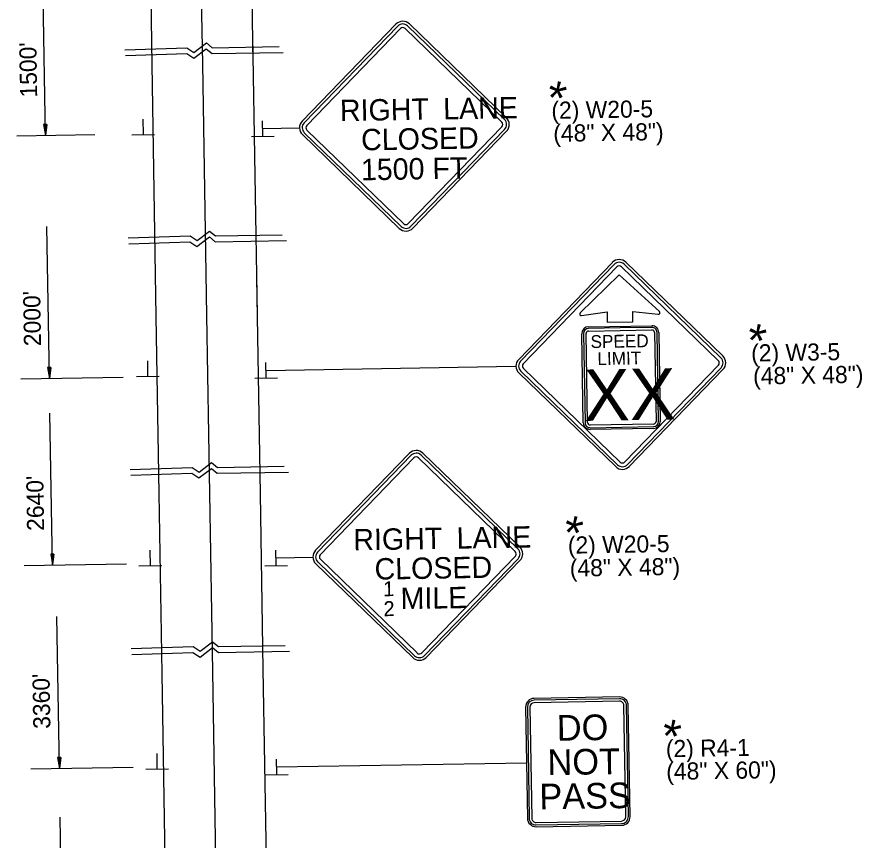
# Model space of a CAD drawing. Extents: x 1676639 to 1677883, y 226447 to 231777.
# Drawn here: x 1677068.7 to 1677365.1, y 228691.4 to 228980 of the extents above; entities that cross this region are included whole.
import ezdxf

# ---------------------------------------------------------------- set-up
doc = ezdxf.new("R2010")
doc.units = 0
for name, color, linetype in [('Default', 7, 'Continuous'), ('P_TC_Signs_Permanent', 7, 'Continuous'), ('P_TC_Signs_Temporary', 7, 'Continuous'), ('R_Annotation', 7, 'Continuous')]:
    doc.layers.add(name, color=color, linetype=linetype)

msp = doc.modelspace()

# ---------------------------------------------------------------- linework, layer by layer
at = {"layer": 'Default'}
for p, q in [((1677116.11, 228963.33), (1677113.41, 229126.42)), ((1677133.84, 228963.62), (1677131.14, 229126.72)), ((1677151.57, 228963.92), (1677148.87, 229127.01)), ((1677078.66, 228938.47), (1677077.78, 228991.7)), ((1677153.03, 228875.59), (1677151.41, 228973.27)), ((1677117.57, 228875.01), (1677116.11, 228963.33)), ((1677135.3, 228875.3), (1677133.84, 228963.62)), ((1677079.17, 228942.31), (1677078.02, 228942.29)), ((1677078.02, 228942.29), (1677078.66, 228938.47)), ((1677078.12, 228942.29), (1677078.65, 228939.11)), ((1677078.21, 228942.29), (1677078.64, 228939.77)), ((1677078.31, 228942.29), (1677078.63, 228940.41)), ((1677078.41, 228942.29), (1677078.62, 228941.05)), ((1677078.5, 228942.3), (1677078.6, 228941.69)), ((1677078.68, 228942.3), (1677078.6, 228941.69)), ((1677078.78, 228942.3), (1677078.62, 228941.05)), ((1677078.88, 228942.3), (1677078.63, 228940.41)), ((1677078.97, 228942.3), (1677078.64, 228939.77)), ((1677079.07, 228942.31), (1677078.65, 228939.11)), ((1677079.17, 228942.31), (1677078.66, 228938.47)), ((1677113.02, 228938.77), (1677112.93, 228944.22)), ((1677154.92, 228938.18), (1677154.83, 228943.62)), ((1677068.67, 228938.31), (1677096.05, 228938.76)), ((1677116.99, 228938.72), (1677109.01, 228938.59)), ((1677158.89, 228938.13), (1677150.91, 228937.99)), ((1677080.07, 228853.29), (1677079.19, 228906.51)), ((1677154.07, 228812.85), (1677152.82, 228888.67)), ((1677118.6, 228812.95), (1677117.57, 228875.01)), ((1677136.34, 228812.9), (1677135.3, 228875.3)), ((1677114.64, 228853.98), (1677114.55, 228859.43)), ((1677156.11, 228853.38), (1677156.02, 228858.83)), ((1677080.58, 228857.12), (1677079.43, 228857.11)), ((1677079.43, 228857.11), (1677080.07, 228853.29)), ((1677079.53, 228857.11), (1677080.06, 228853.93)), ((1677079.63, 228857.11), (1677080.05, 228854.59)), ((1677079.72, 228857.11), (1677080.04, 228855.22)), ((1677079.82, 228857.11), (1677080.03, 228855.87)), ((1677079.92, 228857.11), (1677080.02, 228856.51)), ((1677080.1, 228857.12), (1677080.02, 228856.51)), ((1677080.19, 228857.12), (1677080.03, 228855.87)), ((1677080.29, 228857.12), (1677080.04, 228855.22)), ((1677080.39, 228857.12), (1677080.05, 228854.59)), ((1677080.48, 228857.12), (1677080.06, 228853.93)), ((1677080.58, 228857.12), (1677080.07, 228853.29)), ((1677070.08, 228853.13), (1677105.99, 228853.72)), ((1677118.61, 228853.93), (1677110.63, 228853.8)), ((1677160.08, 228853.33), (1677152.1, 228853.2)), ((1677081.15, 228787.86), (1677080.27, 228841.08)), ((1677119.65, 228749.75), (1677118.6, 228812.95)), ((1677137.37, 228750.51), (1677136.34, 228812.9)), ((1677155.09, 228751.27), (1677154.07, 228812.85)), ((1677081.66, 228791.69), (1677080.52, 228791.67)), ((1677080.52, 228791.67), (1677081.15, 228787.86)), ((1677080.61, 228791.67), (1677081.14, 228788.5)), ((1677080.71, 228791.68), (1677081.13, 228789.15)), ((1677080.81, 228791.68), (1677081.12, 228789.79)), ((1677080.9, 228791.68), (1677081.11, 228790.44)), ((1677081, 228791.68), (1677081.1, 228791.08)), ((1677081.18, 228791.68), (1677081.1, 228791.08)), ((1677081.28, 228791.68), (1677081.11, 228790.44)), ((1677081.38, 228791.69), (1677081.12, 228789.79)), ((1677081.47, 228791.69), (1677081.13, 228789.15)), ((1677081.57, 228791.69), (1677081.14, 228788.5)), ((1677081.66, 228791.69), (1677081.15, 228787.86)), ((1677115.5, 228787.61), (1677115.41, 228793.06)), ((1677159.63, 228787.66), (1677159.54, 228793.1)), ((1677071.17, 228787.69), (1677107.08, 228788.29)), ((1677119.47, 228787.56), (1677111.49, 228787.43)), ((1677163.6, 228787.61), (1677155.62, 228787.47)), ((1677083.56, 228716.52), (1677082.68, 228769.75)), ((1677120.9, 228674.34), (1677119.65, 228749.75)), ((1677138.63, 228674.64), (1677137.37, 228750.51)), ((1677156.36, 228674.93), (1677155.09, 228751.27)), ((1677084.07, 228720.36), (1677082.92, 228720.34)), ((1677082.92, 228720.34), (1677083.56, 228716.52)), ((1677083.02, 228720.34), (1677083.55, 228717.16)), ((1677083.12, 228720.34), (1677083.54, 228717.82)), ((1677083.21, 228720.34), (1677083.53, 228718.46)), ((1677083.31, 228720.35), (1677083.52, 228719.11)), ((1677083.41, 228720.35), (1677083.51, 228719.74)), ((1677083.59, 228720.35), (1677083.51, 228719.74)), ((1677083.68, 228720.35), (1677083.52, 228719.11)), ((1677083.78, 228720.35), (1677083.53, 228718.46)), ((1677083.88, 228720.35), (1677083.54, 228717.82)), ((1677083.98, 228720.36), (1677083.55, 228717.16)), ((1677084.07, 228720.36), (1677083.56, 228716.52)), ((1677117.91, 228716.28), (1677117.82, 228721.73)), ((1677159.82, 228714.35), (1677159.73, 228719.79)), ((1677073.58, 228716.36), (1677109.48, 228716.95)), ((1677121.88, 228716.23), (1677113.9, 228716.1)), ((1677163.79, 228714.3), (1677155.81, 228714.16)), ((1677084.73, 228646.15), (1677083.84, 228699.37))]:
    msp.add_line(p, q, dxfattribs=at)
for points in [[(1677106.57, 228968.51), (1677128.3, 228969.2), (1677130.79, 228967.59), (1677135.15, 228970.89), (1677137.22, 228969.22), (1677160.64, 228969.61)], [(1677106.8, 228966.48), (1677128.25, 228967.17), (1677130.74, 228965.55), (1677135.1, 228968.85), (1677137.16, 228967.19), (1677162.11, 228967.59)], [(1677107.67, 228902.52), (1677129.39, 228903.22), (1677131.88, 228901.6), (1677136.24, 228904.9), (1677138.31, 228903.24), (1677161.73, 228903.62)], [(1677107.89, 228900.49), (1677129.34, 228901.18), (1677131.83, 228899.56), (1677136.19, 228902.86), (1677138.26, 228901.2), (1677163.2, 228901.6)], [(1677108.37, 228821.37), (1677130.09, 228822.06), (1677132.58, 228820.45), (1677136.94, 228823.75), (1677139.01, 228822.08), (1677162.43, 228822.47)], [(1677108.6, 228819.34), (1677130.04, 228820.02), (1677132.53, 228818.41), (1677136.89, 228821.71), (1677138.96, 228820.04), (1677163.9, 228820.45)], [(1677108.74, 228758.53), (1677130.47, 228759.22), (1677132.96, 228757.6), (1677137.32, 228760.9), (1677139.38, 228759.24), (1677162.81, 228759.62)], [(1677108.97, 228756.5), (1677130.41, 228757.18), (1677132.9, 228755.57), (1677137.27, 228758.87), (1677139.33, 228757.2), (1677164.28, 228757.61)]]:
    msp.add_lwpolyline(points, dxfattribs=at)
at = {"layer": 'P_TC_Signs_Permanent'}
for p, q in [((1677277.53, 228893.92), (1677244.67, 228859.96)), ((1677278.2, 228893.27), (1677245.35, 228859.31)), ((1677279.14, 228892.35), (1677246.29, 228858.39)), ((1677314.69, 228859.53), (1677280.73, 228892.38)), ((1677315.61, 228860.47), (1677281.65, 228893.32)), ((1677316.26, 228861.15), (1677282.3, 228894)), ((1677269.18, 228871.39), (1677291.38, 228871.75)), ((1677267.34, 228837.75), (1677266.82, 228868.95)), ((1677293.82, 228869.39), (1677294.34, 228838.2)), ((1677245.4, 228855.86), (1677279.36, 228823.01)), ((1677246.32, 228856.8), (1677280.28, 228823.95)), ((1677281.87, 228823.98), (1677314.72, 228857.94)), ((1677282.81, 228823.06), (1677315.66, 228857.02)), ((1677283.48, 228822.41), (1677316.34, 228856.37)), ((1677244.75, 228855.19), (1677278.71, 228822.33)), ((1677291.98, 228835.76), (1677269.78, 228835.39)), ((1677280.05, 228741.57), (1677250.06, 228741.07)), ((1677280.06, 228740.97), (1677250.07, 228740.47)), ((1677280.08, 228740.07), (1677250.08, 228739.57)), ((1677247.11, 228738.02), (1677247.75, 228699.03)), ((1677247.71, 228738.03), (1677248.35, 228699.04)), ((1677248.61, 228738.05), (1677249.25, 228699.05)), ((1677282.25, 228699.6), (1677281.6, 228738.59)), ((1677283.15, 228699.61), (1677282.5, 228738.61)), ((1677283.75, 228699.62), (1677283.1, 228738.62)), ((1677250.78, 228697.58), (1677280.77, 228698.07)), ((1677250.79, 228696.68), (1677280.79, 228697.17)), ((1677250.8, 228696.08), (1677280.8, 228696.57))]:
    msp.add_line(p, q, dxfattribs=at)
for points in [[(1677294.04, 228876.71), (1677279.95, 228889.57), (1677266.29, 228876.25)], [(1677266.76, 228875.29), (1677275.7, 228876.56), (1677275.76, 228873), (1677284.76, 228873.15), (1677284.7, 228876.7), (1677293.6, 228875.74)], [(1677291.39, 228871.15), (1677280.29, 228870.97), (1677269.19, 228870.79)], [(1677267.42, 228868.96), (1677267.94, 228837.76)], [(1677268.84, 228837.78), (1677268.32, 228868.97)], [(1677269.21, 228869.89), (1677280.31, 228870.07), (1677291.41, 228870.25)], [(1677292.32, 228869.37), (1677292.84, 228838.17)], [(1677293.74, 228838.19), (1677293.22, 228869.38)], [(1677291.95, 228837.26), (1677269.76, 228836.89)], [(1677269.77, 228835.99), (1677291.97, 228836.36)]]:
    msp.add_lwpolyline(points, dxfattribs=at)
for centre, radius, start, end in [((1677279.95, 228891.57), 3.38, 45.9497, 135.9497), ((1677279.95, 228891.57), 2.44, 45.9497, 135.9497), ((1677279.95, 228891.57), 1.13, 45.9497, 135.9497), ((1677293.66, 228876.3), 0.563, 263.8247, 47.6381), ((1677266.68, 228875.85), 0.563, 134.2614, 278.0747), ((1677269.22, 228868.99), 2.4, 90.9497, 180.9497), ((1677269.22, 228868.99), 1.8, 90.9497, 180.9497), ((1677291.42, 228869.35), 2.4, 0.9497, 90.9497), ((1677291.42, 228869.35), 1.8, 0.9497, 90.9497), ((1677269.22, 228868.99), 0.9, 90.9497, 180.9497), ((1677291.42, 228869.35), 0.9, 0.9497, 90.9497), ((1677247.1, 228857.61), 3.38, 135.9497, 225.9497), ((1677247.1, 228857.61), 2.44, 135.9497, 225.9497), ((1677313.91, 228858.72), 1.13, 315.9497, 45.9497), ((1677313.91, 228858.72), 2.44, 315.9497, 45.9497), ((1677313.91, 228858.72), 3.38, 315.9497, 45.9497), ((1677247.1, 228857.61), 1.13, 135.9497, 225.9497), ((1677291.94, 228838.16), 0.9, 270.9497, 0.9497), ((1677291.94, 228838.16), 1.8, 270.9497, 0.9497), ((1677291.94, 228838.16), 2.4, 270.9497, 0.9497), ((1677269.74, 228837.79), 2.4, 180.9497, 270.9497), ((1677269.74, 228837.79), 1.8, 180.9497, 270.9497), ((1677269.74, 228837.79), 0.9, 180.9497, 270.9497), ((1677281.06, 228824.76), 2.44, 225.9497, 315.9497), ((1677281.06, 228824.76), 1.13, 225.9497, 315.9497), ((1677281.06, 228824.76), 3.38, 225.9497, 315.9497), ((1677250.11, 228738.07), 3, 90.9497, 180.9497), ((1677250.11, 228738.07), 2.4, 90.9497, 180.9497), ((1677280.1, 228738.57), 3, 0.9497, 90.9497), ((1677280.1, 228738.57), 2.4, 0.9497, 90.9497), ((1677280.1, 228738.57), 1.5, 0.9497, 90.9497), ((1677250.11, 228738.07), 1.5, 90.9497, 180.9497), ((1677250.75, 228699.08), 3, 180.9497, 270.9497), ((1677250.75, 228699.08), 2.4, 180.9497, 270.9497), ((1677250.75, 228699.08), 1.5, 180.9497, 270.9497), ((1677280.75, 228699.57), 1.5, 270.9497, 0.9497), ((1677280.75, 228699.57), 2.4, 270.9497, 0.9497), ((1677280.75, 228699.57), 3, 270.9497, 0.9497)]:
    msp.add_arc(centre, radius, start, end, dxfattribs=at)
at = {"layer": 'P_TC_Signs_Temporary'}
for p, q in [((1677168.75, 228943.52), (1677201.6, 228977.48)), ((1677206.38, 228977.56), (1677240.34, 228944.7)), ((1677169.43, 228942.87), (1677202.28, 228976.83)), ((1677170.37, 228941.95), (1677203.22, 228975.91)), ((1677204.81, 228975.94), (1677238.77, 228943.09)), ((1677205.73, 228976.88), (1677239.69, 228944.03)), ((1677202.79, 228905.89), (1677168.83, 228938.74)), ((1677203.44, 228906.57), (1677169.48, 228939.42)), ((1677204.36, 228907.51), (1677170.4, 228940.36)), ((1677238.8, 228941.5), (1677205.95, 228907.54)), ((1677239.74, 228940.58), (1677206.89, 228906.62)), ((1677240.42, 228939.93), (1677207.56, 228905.97)), ((1677173.46, 228793), (1677206.31, 228826.96)), ((1677174.14, 228792.34), (1677206.99, 228826.3)), ((1677210.44, 228826.36), (1677244.4, 228793.51)), ((1677211.09, 228827.04), (1677245.05, 228794.18)), ((1677175.08, 228791.43), (1677207.93, 228825.39)), ((1677209.52, 228825.42), (1677243.48, 228792.57)), ((1677243.51, 228790.98), (1677210.66, 228757.02)), ((1677207.5, 228755.37), (1677173.54, 228788.22)), ((1677208.15, 228756.05), (1677174.19, 228788.9)), ((1677209.07, 228756.99), (1677175.11, 228789.84)), ((1677244.45, 228790.06), (1677211.6, 228756.1)), ((1677245.13, 228789.41), (1677212.27, 228755.45))]:
    msp.add_line(p, q, dxfattribs=at)
for centre, radius, start, end in [((1677204.03, 228975.13), 3.38, 45.9497, 135.9497), ((1677204.03, 228975.13), 2.44, 45.9497, 135.9497), ((1677204.03, 228975.13), 1.13, 45.9497, 135.9497), ((1677237.99, 228942.28), 3.38, 315.9497, 45.9497), ((1677171.18, 228941.17), 3.38, 135.9497, 225.9497), ((1677171.18, 228941.17), 2.44, 135.9497, 225.9497), ((1677171.18, 228941.17), 1.12, 135.9497, 225.9497), ((1677237.99, 228942.28), 1.12, 315.9497, 45.9497), ((1677237.99, 228942.28), 2.44, 315.9497, 45.9497), ((1677205.14, 228908.32), 2.44, 225.9497, 315.9497), ((1677205.14, 228908.32), 1.13, 225.9497, 315.9497), ((1677205.14, 228908.32), 3.38, 225.9497, 315.9497), ((1677208.74, 228824.61), 3.38, 45.9497, 135.9497), ((1677208.74, 228824.61), 2.44, 45.9497, 135.9497), ((1677208.74, 228824.61), 1.13, 45.9497, 135.9497), ((1677242.7, 228791.76), 2.44, 315.9497, 45.9497), ((1677242.7, 228791.76), 3.38, 315.9497, 45.9497), ((1677175.89, 228790.65), 3.38, 135.9497, 225.9497), ((1677175.89, 228790.65), 2.44, 135.9497, 225.9497), ((1677175.89, 228790.65), 1.12, 135.9497, 225.9497), ((1677242.7, 228791.76), 1.12, 315.9497, 45.9497), ((1677209.85, 228757.8), 3.38, 225.9497, 315.9497), ((1677209.85, 228757.8), 2.44, 225.9497, 315.9497), ((1677209.85, 228757.8), 1.13, 225.9497, 315.9497)]:
    msp.add_arc(centre, radius, start, end, dxfattribs=at)
at = {"layer": 'R_Annotation'}
for p, q in [((1677154.88, 228940.9), (1677167.8, 228941.11)), ((1677156.07, 228856.1), (1677243.72, 228857.56)), ((1677159.59, 228790.38), (1677172.51, 228790.59)), ((1677159.77, 228717.07), (1677247.43, 228718.52))]:
    msp.add_line(p, q, dxfattribs=at)

# ---------------------------------------------------------------- texts
at = {"layer": 'Default'}
for s, p in [("1500'", (1677075.8, 228951.8)), ("2000'", (1677077.16, 228864.63)), ("2640'", (1677078.24, 228799.85)), ("3360'", (1677080.43, 228730.44))]:
    msp.add_text(s, height=6, rotation=90.9497, dxfattribs=at).set_placement(p)
at = {"layer": 'P_TC_Signs_Permanent'}
for s, height, rotation, p in [('SPEED', 4.5, 0.9497, (1677269.91, 228863.9)), ('LIMIT', 4.5, 0.9497, (1677272.32, 228857.94)), ('XX', 18, 0.9497, (1677267.69, 228838.36)), ('DO', 9, 0.9497, (1677258.13, 228726.2)), ('NOT', 9, 0.9094, (1677254.85, 228714.15)), ('PASS', 9, 0.9497, (1677251.99, 228702.1))]:
    msp.add_text(s, height=height, rotation=rotation, dxfattribs=at).set_placement(p)
at = {"layer": 'P_TC_Signs_Temporary'}
for s, height, p in [('RIGHT\u2002LANE', 7.5, (1677182.03, 228943.48)), ('CLOSED', 7.5, (1677189.47, 228933.22)), ('1500 FT', 7.5, (1677189.38, 228922.72)), ('RIGHT\u2002LANE', 7.5, (1677186.74, 228792.96)), ('CLOSED', 7.5, (1677194.18, 228782.7)), ('1', 5.25, (1677197.18, 228776.88)), (' MILE', 7.5, (1677200.52, 228772.31)), ('2', 5.25, (1677197.29, 228769.88))]:
    msp.add_text(s, height=height, rotation=0.9497, dxfattribs=at).set_placement(p)
at = {"layer": 'R_Annotation'}
for s, height, rotation, p in [('*', 12, 135.9497, (1677266.71, 228958.47)), ('(2) W20-5', 6, 0.9497, (1677256.19, 228944.26)), ('(48" X 48")', 6, 0.9497, (1677256.86, 228936.21)), ('*', 12, 135.9497, (1677336.8, 228873.38)), ('(2) W3-5', 6, 0.9497, (1677326.27, 228859.16)), ('(48" X 48")', 6, 0.9497, (1677326.95, 228851.12)), ('*', 12, 135.9497, (1677272.5, 228806.01)), ('(2) W20-5', 6, 0.9497, (1677261.97, 228791.8)), ('(48" X 48")', 6, 0.9497, (1677262.65, 228783.75)), ('*', 12, 135.9497, (1677306.88, 228734.64)), ('(2) R4-1', 6, 0.9497, (1677296.35, 228720.42)), ('(48" X 60")', 6, 0.9497, (1677296.48, 228712.48))]:
    msp.add_text(s, height=height, rotation=rotation, dxfattribs=at).set_placement(p)

doc.saveas('drawing.dxf')
